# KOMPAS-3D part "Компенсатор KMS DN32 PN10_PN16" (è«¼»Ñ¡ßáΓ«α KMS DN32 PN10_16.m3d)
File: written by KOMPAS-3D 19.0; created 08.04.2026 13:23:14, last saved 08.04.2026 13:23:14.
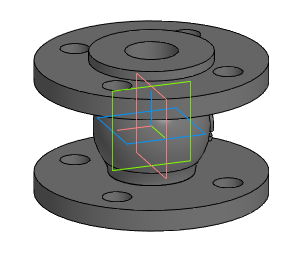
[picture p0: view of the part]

Document properties: Автор: Энергия; Полное имя файла: Z:\3.Личные\kachalov\3d для проектировщиков\7.1 Компенсатор\stp_Компенсатор KSM\Компенсатор KMS DN32 PN10_16.m3d

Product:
- Part/product: Компенсатор KMS DN32 PN10_PN16

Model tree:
1. Операция без истории:1  (labels: Компенсатор KMS DN32 PN10_PN16)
